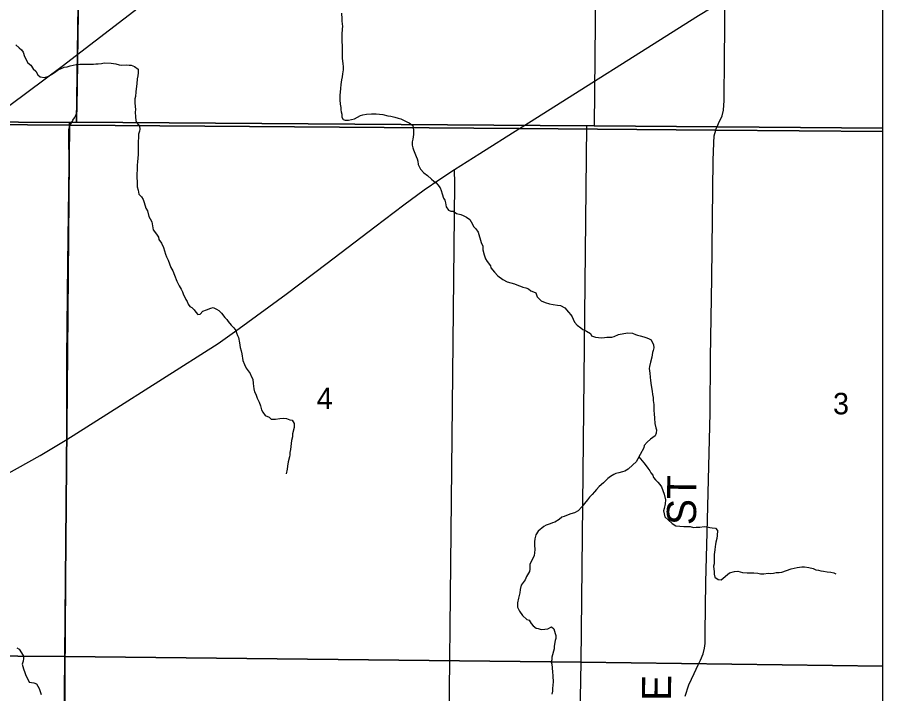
# Model space of a CAD drawing. Extents: x -8.5 to 18.7, y -20.3 to 7.
# Drawn here: x 15.375 to 18.741, y -1.005 to 1.627 of the extents above; entities that cross this region are included whole.
import ezdxf

# ---------------------------------------------------------------- set-up
doc = ezdxf.new("R2010")
doc.units = 0
for name, color, linetype in [('Default', 7, 'Continuous'), ('GM_X_Corporation', 7, 'Continuous'), ('GM_X_County_Road', 7, 'Continuous'), ('GM_X_County_Road_Text', 7, 'Continuous'), ('GM_X_Minor_River', 7, 'Continuous'), ('GM_X_Rail_Line', 7, 'Continuous'), ('GM_X_Section', 7, 'Continuous'), ('GM_X_Section_Text', 7, 'Continuous'), ('GM_X_State_Route', 7, 'Continuous'), ('GM_X_Township_Road', 7, 'Continuous'), ('SH_Cut_Line', 7, 'Continuous')]:
    doc.layers.add(name, color=color, linetype=linetype)

msp = doc.modelspace()

# ---------------------------------------------------------------- linework, layer by layer
at = {"layer": 'Default'}
for points in [[(18.7413, 1.196), (18.7413, 3.1985), (17.6382, 3.208), (17.6187, 1.2053)], [(18.7413, -0.8985), (18.7413, 1.196), (17.6187, 1.2053), (17.5899, 1.2047), (17.5677, -0.8821)], [(18.7413, -2.8883), (18.7413, -0.8985), (17.5677, -0.8821), (17.5292, -2.8892)]]:
    msp.add_lwpolyline(points, close=True, dxfattribs=at)
at = {"layer": 'GM_X_Corporation'}
msp.add_lwpolyline([(18.7413, 1.1834), (18.7413, 6.938), (11.7049, 6.938), (11.6732, 5.0475), (11.6689, 4.6186), (11.6686, 4.5917), (11.6653, 4.2586), (11.64, 3.2551), (11.6132, 2.2462), (11.5871, 1.2389), (13.587, 1.2234), (15.5804, 1.208), (17.3261, 1.1944), (18.0915, 1.1885)], close=True, dxfattribs=at)
msp.add_lwpolyline([(18.7413, -10.9039), (18.7413, 1.1834), (18.0915, 1.1885), (17.3261, 1.1944), (15.5804, 1.208), (13.587, 1.2234), (11.5871, 1.2389), (11.5625, -0.7587), (11.5622, -0.7805), (11.5527, -2.1798)], dxfattribs=at)
at = {"layer": 'GM_X_County_Road'}
for points in [[(18.1003, 1.2079), (18.1028, 1.2134), (18.1171, 1.2442), (18.1227, 1.2661), (18.1241, 1.304), (18.1261, 1.4721), (18.1267, 1.5823), (18.1273, 1.6332), (18.1285, 1.6812), (18.1302, 1.6994)], [(17.9735, -1.0143), (17.9878, -0.9711), (18.0086, -0.9265), (18.024, -0.8934), (18.0333, -0.8741), (18.0425, -0.8505), (18.0484, -0.8278), (18.0504, -0.8104), (18.0504, -0.7669), (18.0534, -0.5706), (18.0593, -0.3288), (18.0697, 0.088), (18.0722, 0.3029), (18.0767, 0.612), (18.0795, 0.8445), (18.0821, 1.0695), (18.0846, 1.1393), (18.0863, 1.1654), (18.092, 1.1874), (18.0936, 1.1935), (18.1003, 1.2079)]]:
    msp.add_lwpolyline(points, dxfattribs=at)
at = {"layer": 'GM_X_Minor_River'}
for points in [[(16.6359, 1.6429), (16.6383, 1.6209), (16.6383, 1.6118), (16.6399, 1.5913), (16.6392, 1.5821), (16.6378, 1.5601), (16.6379, 1.5366), (16.6388, 1.5123), (16.6396, 1.4993), (16.639, 1.4841), (16.639, 1.4667), (16.6414, 1.4469), (16.643, 1.434), (16.6431, 1.4226), (16.6409, 1.4074), (16.6386, 1.3953), (16.6364, 1.3838), (16.6335, 1.3656), (16.632, 1.3496), (16.6313, 1.336), (16.6299, 1.3238), (16.63, 1.3056), (16.6308, 1.2889), (16.6332, 1.2767), (16.634, 1.2676), (16.6355, 1.2592), (16.6371, 1.2501), (16.6379, 1.238), (16.6425, 1.2289), (16.6509, 1.2266), (16.6638, 1.2275), (16.6873, 1.2321), (16.7108, 1.2452), (16.7191, 1.2482), (16.7335, 1.2498), (16.7525, 1.2514), (16.7707, 1.2515), (16.7965, 1.2486), (16.8171, 1.2434), (16.8284, 1.2419), (16.8444, 1.2382), (16.8573, 1.2352), (16.8672, 1.2322), (16.8824, 1.2247), (16.8908, 1.2202), (16.8999, 1.2164), (16.9144, 1.2059), (16.9168, 1.1876), (16.9161, 1.1717), (16.9139, 1.1534), (16.9117, 1.1428), (16.911, 1.1299), (16.9133, 1.1192), (16.9164, 1.1109), (16.9218, 1.0988), (16.9272, 1.0859), (16.931, 1.076), (16.9333, 1.0677), (16.9349, 1.054), (16.9395, 1.0442), (16.9441, 1.0358), (16.9563, 1.0222), (16.9708, 1.0109), (16.9868, 0.9973), (16.9952, 0.9897), (17.0044, 0.9829), (17.0112, 0.9746), (17.0196, 0.9632), (17.0243, 0.9526), (17.0281, 0.9397), (17.0335, 0.9238), (17.0381, 0.9155), (17.0404, 0.9048), (17.0436, 0.8897), (17.0527, 0.8768), (17.0611, 0.873), (17.0702, 0.8723), (17.0839, 0.864), (17.0999, 0.8595), (17.1098, 0.8565), (17.1227, 0.849), (17.1349, 0.84), (17.1456, 0.8225), (17.1502, 0.8134), (17.1586, 0.8044), (17.1678, 0.7915)], [(15.3701, 1.5207), (15.3824, 1.5078), (15.3923, 1.501), (15.3976, 1.492), (15.403, 1.4753), (15.4161, 1.4503), (15.4275, 1.4412), (15.4367, 1.4268), (15.4473, 1.417), (15.4558, 1.4033)], [(15.4558, 1.4033), (15.4642, 1.3958), (15.4809, 1.3928), (15.4945, 1.3967), (15.5089, 1.4051), (15.5202, 1.4128), (15.5354, 1.4242), (15.5437, 1.4273), (15.5573, 1.4334), (15.5687, 1.435), (15.5816, 1.4381), (15.6044, 1.4435), (15.618, 1.4444), (15.6309, 1.4452), (15.6408, 1.4452), (15.6514, 1.4445), (15.6712, 1.4454), (15.6803, 1.4462), (15.6894, 1.4462), (15.7023, 1.447), (15.7137, 1.4494), (15.7402, 1.4487), (15.7493, 1.448), (15.7585, 1.4458), (15.7714, 1.4428), (15.7813, 1.4413), (15.8002, 1.4422), (15.8101, 1.4407), (15.8185, 1.4408), (15.8314, 1.4355), (15.8451, 1.4249), (15.846, 1.4113), (15.8445, 1.3999), (15.8415, 1.3877), (15.8401, 1.3679), (15.8386, 1.3588), (15.8365, 1.3375), (15.835, 1.3185), (15.8328, 1.3101), (15.8329, 1.2934), (15.8345, 1.2684), (15.8338, 1.2577), (15.8347, 1.2395), (15.8363, 1.2251), (15.8401, 1.2167), (15.8508, 1.2031), (15.8516, 1.1925), (15.8509, 1.1841), (15.8472, 1.1719), (15.8464, 1.1621), (15.8458, 1.1408), (15.8458, 1.1302), (15.8452, 1.1112), (15.8453, 1.0914), (15.8438, 1.08), (15.8431, 1.064), (15.8417, 1.0534), (15.841, 1.0314), (15.8403, 1.0207), (15.8397, 0.9995), (15.8412, 0.9903), (15.8421, 0.9668), (15.846, 0.9547), (15.8483, 0.9395), (15.8582, 0.9281), (15.8651, 0.9175), (15.8682, 0.9069), (15.8752, 0.8841), (15.8813, 0.8743), (15.8875, 0.8523), (15.8928, 0.8424), (15.8982, 0.8311), (15.9044, 0.8007), (15.9167, 0.7833), (15.9243, 0.7719), (15.9259, 0.7628), (15.9366, 0.7477), (15.9443, 0.731), (15.952, 0.7052), (15.9551, 0.6953), (15.962, 0.6817), (15.9727, 0.6536), (15.9804, 0.6408), (15.9873, 0.6233), (15.9965, 0.5998), (16.005, 0.5824), (16.0126, 0.5687), (16.018, 0.5589), (16.0219, 0.5468), (16.0272, 0.5384), (16.0311, 0.5293), (16.0357, 0.521), (16.0395, 0.5111), (16.0464, 0.502), (16.0548, 0.4975), (16.0631, 0.4884), (16.07, 0.4801), (16.0777, 0.4703), (16.0868, 0.4718), (16.0966, 0.4833), (16.111, 0.4887)], [(17.1678, 0.7915), (17.1801, 0.7505), (17.1855, 0.7361), (17.1864, 0.7224), (17.191, 0.7027), (17.1964, 0.6868), (17.2025, 0.6762), (17.2163, 0.6603), (17.2178, 0.6519), (17.2316, 0.6353), (17.2438, 0.6209), (17.2636, 0.6066), (17.2811, 0.5983), (17.3092, 0.5901), (17.3245, 0.5833), (17.3328, 0.5803), (17.342, 0.5773), (17.3534, 0.5743), (17.364, 0.5706), (17.3732, 0.563), (17.3831, 0.5585), (17.3922, 0.5547), (17.3968, 0.5396), (17.4128, 0.5237), (17.4288, 0.5169), (17.4448, 0.5117), (17.4592, 0.5095), (17.4759, 0.5073), (17.4881, 0.5051), (17.5048, 0.496), (17.5193, 0.4801), (17.5285, 0.4695), (17.5331, 0.4612), (17.5369, 0.4521), (17.5431, 0.4407), (17.553, 0.4294), (17.5667, 0.4181), (17.5751, 0.412), (17.5888, 0.406), (17.6048, 0.3962), (17.6086, 0.3879), (17.6246, 0.3819), (17.6474, 0.3797), (17.6588, 0.3805), (17.6686, 0.3821), (17.6876, 0.3829), (17.6967, 0.3845), (17.7134, 0.3922), (17.749, 0.3992), (17.7688, 0.3977), (17.7794, 0.3925), (17.7878, 0.3895), (17.7984, 0.388), (17.8121, 0.3843), (17.8205, 0.3813), (17.8304, 0.3768), (17.8403, 0.3715), (17.8502, 0.3525), (17.851, 0.3412), (17.8481, 0.3305), (17.8466, 0.3221), (17.8436, 0.3039), (17.8384, 0.2856), (17.834, 0.2681), (17.8332, 0.2598), (17.8356, 0.2423), (17.8372, 0.2264), (17.838, 0.2142), (17.8412, 0.1937), (17.8443, 0.1725), (17.8466, 0.1588), (17.8482, 0.1474), (17.849, 0.1353), (17.8506, 0.1201), (17.8515, 0.1079), (17.8515, 0.0973), (17.8531, 0.0836), (17.8539, 0.0669), (17.8556, 0.0464), (17.8587, 0.0297), (17.861, 0.0214), (17.8603, 0.0092), (17.8558, -0.0022), (17.8376, -0.0145), (17.8248, -0.0267), (17.8142, -0.0389), (17.812, -0.0488), (17.7977, -0.0747), (17.7887, -0.0914), (17.7819, -0.1029), (17.7698, -0.1143), (17.7517, -0.1311), (17.738, -0.1388), (17.7297, -0.1411), (17.7145, -0.145), (17.7039, -0.1488), (17.6956, -0.1526), (17.6827, -0.1595), (17.6729, -0.1679), (17.6638, -0.1763), (17.6555, -0.184)], [(16.111, 0.4887), (16.1284, 0.4948), (16.1375, 0.4979), (16.1504, 0.4919), (16.1588, 0.4859), (16.1695, 0.4753), (16.1825, 0.4594), (16.1909, 0.4511), (16.1962, 0.4427), (16.2077, 0.4291), (16.2176, 0.4185), (16.226, 0.4079), (16.2276, 0.3996), (16.2322, 0.389), (16.2353, 0.3806), (16.2399, 0.3609), (16.2423, 0.3419), (16.2462, 0.329), (16.2485, 0.3169), (16.2524, 0.2918), (16.2586, 0.2766), (16.2655, 0.2615), (16.2739, 0.2509), (16.2808, 0.2411), (16.2854, 0.2304), (16.2915, 0.2183), (16.2931, 0.2024), (16.2955, 0.1819), (16.2986, 0.169), (16.3032, 0.1599), (16.3078, 0.1455), (16.3162, 0.1288), (16.3216, 0.1151), (16.3255, 0.0992), (16.3309, 0.0901), (16.3393, 0.078), (16.3545, 0.0712), (16.3629, 0.0637), (16.3796, 0.063), (16.397, 0.0653), (16.4122, 0.0669), (16.4228, 0.0662), (16.4358, 0.0602), (16.4441, 0.0587), (16.4518, 0.0458), (16.4519, 0.0314), (16.4459, 0.0063), (16.4452, -0.0051), (16.4423, -0.0203), (16.4379, -0.0545), (16.4357, -0.0659), (16.4349, -0.075), (16.4335, -0.0834), (16.429, -0.1032), (16.4261, -0.1199), (16.4254, -0.132), (16.4216, -0.1495)], [(17.7928, -0.0837), (17.8123, -0.1065), (17.8215, -0.1179), (17.8276, -0.1277), (17.8352, -0.1375), (17.8398, -0.1459), (17.8467, -0.155), (17.8498, -0.1641), (17.8574, -0.1731), (17.8673, -0.1815), (17.875, -0.1905), (17.8811, -0.1996), (17.8919, -0.2284), (17.8965, -0.2512), (17.8958, -0.2657), (17.8914, -0.2847), (17.8891, -0.2938), (17.8946, -0.3173), (17.9083, -0.3294), (17.922, -0.3423), (17.9373, -0.3513), (17.9684, -0.355), (17.9919, -0.3548), (18.0056, -0.3578), (18.0162, -0.357), (18.0307, -0.3577), (18.0466, -0.3546), (18.0588, -0.356), (18.0694, -0.3583), (18.0778, -0.3598), (18.0914, -0.3612), (18.0991, -0.3703), (18.0976, -0.39), (18.0962, -0.4014), (18.0925, -0.4151), (18.091, -0.4243), (18.0903, -0.4326), (18.0888, -0.4455), (18.0873, -0.4547), (18.0859, -0.463), (18.0852, -0.479), (18.0853, -0.4995), (18.0831, -0.5094), (18.0839, -0.5208), (18.0854, -0.5299), (18.0862, -0.5398), (18.0886, -0.5511), (18.1008, -0.561), (18.1137, -0.5617), (18.1454, -0.5342), (18.1651, -0.5295), (18.1773, -0.5279), (18.1955, -0.5332), (18.2138, -0.5346), (18.2403, -0.5352), (18.2555, -0.5359), (18.2662, -0.5382), (18.2791, -0.5389), (18.2958, -0.5365), (18.3041, -0.5372), (18.317, -0.5356), (18.3269, -0.5333), (18.3383, -0.5333), (18.3489, -0.5324), (18.3671, -0.5263), (18.3853, -0.5194), (18.4088, -0.5139), (18.4262, -0.5116), (18.4376, -0.5115), (18.4543, -0.5145), (18.4703, -0.5182), (18.4817, -0.5227), (18.4916, -0.5249), (18.5007, -0.5264), (18.5106, -0.5286), (18.525, -0.5309), (18.5394, -0.5323), (18.5508, -0.5345), (18.5592, -0.539)], [(17.6555, -0.184), (17.6389, -0.1985), (17.6276, -0.2107), (17.62, -0.2199), (17.611, -0.2305), (17.6004, -0.2405), (17.5928, -0.2511), (17.5815, -0.2649), (17.571, -0.2786), (17.5574, -0.2931), (17.5422, -0.3007), (17.5286, -0.3054), (17.518, -0.3092), (17.5028, -0.3154), (17.493, -0.3177), (17.4831, -0.3269), (17.4665, -0.3376), (17.4566, -0.3399), (17.4475, -0.3437), (17.4324, -0.3491), (17.4233, -0.3545), (17.4014, -0.3728), (17.3923, -0.3873), (17.3879, -0.4025), (17.3872, -0.4147), (17.3865, -0.4276), (17.3888, -0.4435), (17.3874, -0.4565), (17.3851, -0.4679), (17.3746, -0.4915), (17.3694, -0.5014), (17.3695, -0.5204), (17.368, -0.5302), (17.3559, -0.5493), (17.3507, -0.5615), (17.3356, -0.5828), (17.3319, -0.5995), (17.3304, -0.6125), (17.3245, -0.6338), (17.3208, -0.6513), (17.3209, -0.6687), (17.3293, -0.6846), (17.34, -0.7005), (17.3568, -0.7164), (17.3659, -0.7194), (17.3736, -0.7323), (17.3819, -0.7406), (17.3934, -0.7497), (17.4017, -0.7519), (17.4131, -0.7549), (17.4268, -0.7541), (17.4389, -0.7525), (17.4526, -0.7448), (17.4617, -0.7532), (17.4671, -0.7706), (17.4694, -0.7789), (17.4695, -0.7903), (17.4673, -0.7987), (17.4636, -0.8208), (17.4629, -0.8306), (17.4547, -0.8633), (17.454, -0.8732), (17.4525, -0.8816), (17.4548, -0.8907), (17.4572, -0.9203), (17.4581, -0.9362), (17.459, -0.9598), (17.4583, -0.9712), (17.4568, -0.9864), (17.4569, -0.9955), (17.4546, -1.0069)], [(15.3735, -0.8268), (15.3827, -0.8313), (15.3987, -0.8563), (15.3996, -0.8685), (15.3981, -0.8791), (15.3944, -0.8905), (15.3998, -0.9087), (15.4044, -0.9231), (15.4082, -0.9345), (15.4159, -0.9482), (15.422, -0.9603), (15.4395, -0.9632), (15.4502, -0.967), (15.4548, -0.9753), (15.4601, -0.9844), (15.4632, -0.9928), (15.4678, -1.0087)]]:
    msp.add_lwpolyline(points, dxfattribs=at)
at = {"layer": 'GM_X_Rail_Line'}
msp.add_lwpolyline([(9.8265, -3.4832), (9.9554, -3.3738), (10.2236, -3.1276), (10.7275, -2.6809), (11.4033, -2.0504), (11.764, -1.7469), (11.984, -1.5594), (12.7991, -0.8182), (13.6363, -0.0615), (14.079, 0.3384), (14.2522, 0.47), (14.4319, 0.6106), (14.5413, 0.6862), (15.5503, 1.4365), (16.5816, 2.231), (17.7899, 3.0985), (18.6545, 3.7446), (18.7413, 3.8103)], dxfattribs=at)
at = {"layer": 'GM_X_Section'}
for points in [[(13.6222, 3.2394), (15.6347, 3.2252), (15.6061, 1.2188), (15.5788, 1.2174), (13.5966, 1.2307)], [(17.6382, 3.208), (17.6187, 1.2053), (17.5899, 1.2047), (15.6061, 1.2188), (15.6347, 3.2252)], [(13.5754, 1.2308), (13.5966, 1.2307), (15.5788, 1.2174), (15.5605, -0.8603), (13.5442, -0.8461)], [(15.5788, 1.2174), (15.6061, 1.2188), (17.5899, 1.2047), (17.5677, -0.8821), (15.5605, -0.8603)], [(13.5442, -0.8461), (15.5605, -0.8603), (15.5425, -2.8599), (13.5383, -2.851)], [(15.5605, -0.8603), (17.5677, -0.8821), (17.5292, -2.8892), (15.5425, -2.8599)]]:
    msp.add_lwpolyline(points, close=True, dxfattribs=at)
at = {"layer": 'GM_X_State_Route'}
for points in [[(17.0758, 1.0347), (17.174, 1.0971), (17.3266, 1.1933), (17.3392, 1.2012), (18.0252, 1.6343), (18.1302, 1.6994), (18.326, 1.7949), (18.4545, 1.8571), (18.5035, 1.8849), (18.5504, 1.9208), (18.5913, 1.9576), (18.6446, 2.0067), (18.7288, 2.0849), (18.7413, 2.0972)], [(13.7849, -1.0414), (13.9812, -0.9303), (14.0844, -0.8669), (14.347, -0.6902), (14.4407, -0.6341), (14.8373, -0.4147), (15.0342, -0.3081), (15.2305, -0.2077), (15.4645, -0.0776), (15.5685, -0.0156), (15.7241, 0.0825), (16.1569, 0.3571), (16.2382, 0.416), (16.4217, 0.5495), (16.581, 0.6707), (16.7661, 0.812), (16.8794, 0.8973), (16.9585, 0.9556), (17.019, 0.9978), (17.0758, 1.0347)]]:
    msp.add_lwpolyline(points, dxfattribs=at)
at = {"layer": 'GM_X_Township_Road'}
for points in [[(15.5918, 1.2263), (15.5976, 1.2357), (15.6042, 1.2483), (15.6077, 1.2624), (15.6088, 1.2819), (15.6091, 1.358), (15.6209, 2.2271)], [(15.5443, -3.3501), (15.5685, -0.0156), (15.5686, 0.2994), (15.5725, 0.6708), (15.5776, 1.0534), (15.5759, 1.1711), (15.5763, 1.1903), (15.5798, 1.205), (15.5808, 1.2068), (15.5895, 1.2225), (15.5918, 1.2263)], [(17.0396, -2.5962), (17.0766, 0.9795), (17.0758, 1.0347)]]:
    msp.add_lwpolyline(points, dxfattribs=at)
at = {"layer": 'SH_Cut_Line'}
msp.add_lwpolyline([(18.7413, -10.9039), (18.7413, 6.938), (-8.4587, 6.938)], dxfattribs=at)

# ---------------------------------------------------------------- texts
at = {"layer": 'GM_X_County_Road_Text'}
for s, rotation, p in [('ST', 89.4097, (18.0151, -0.3493)), ('PICKLE', 89.6078, (17.9151, -1.4728))]:
    msp.add_text(s, height=0.11364, rotation=rotation, dxfattribs=at).set_placement(p)
at = {"layer": 'GM_X_Section_Text'}
for s, p in [('4', (16.5398, 0.1026)), ('3', (18.5481, 0.082))]:
    msp.add_text(s, height=0.0837, rotation=0, dxfattribs=at).set_placement(p)

doc.saveas('drawing.dxf')
